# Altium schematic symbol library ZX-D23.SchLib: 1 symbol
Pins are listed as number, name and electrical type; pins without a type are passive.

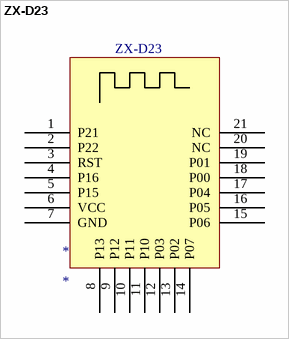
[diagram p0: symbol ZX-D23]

## ZX-D23
designator *
pins: 1 P21 "TX/串口发送", 2 P22 "RX/串口接收", 3 RST "复位脚(低电平有效)", 4 P16 "定制输入输出引脚", 5 P15 "定制输入输出引脚", 6 VCC "电源 (1.7- 3.6V)", 7 GND "地", 8 P13 "定制输入输出引脚", 9 P12 "定制输入输出引脚", 10 P11 "低功耗模式引脚(未连接状态下有效)", 11 P10 "LED状态指示灯引脚", 12 P03 "功能输入按键引脚", 13 P02 "蓝牙连接状态输出引脚", 14 P07 "AT选择引脚", 15 P06 "定制输入输出引脚", 16 P05 "定制输入输出引脚", 17 P04 "定制输入输出引脚", 18 P00 "定制输入输出引脚", 19 P01 "定制输入输出引脚", 20 NC, 21 NC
